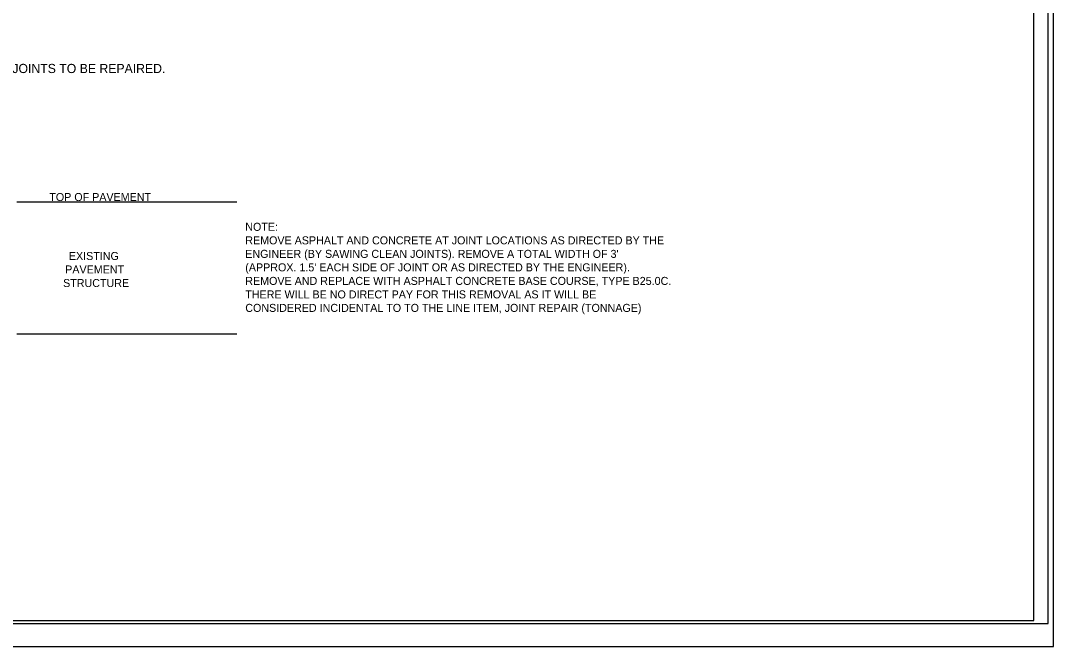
# Model space of a CAD drawing. Extents: x 2455709 to 2456046, y 594728 to 594947.
# Drawn here: x 2455864.9 to 2456045.5, y 594727.6 to 594837 of the extents above; entities that cross this region are included whole.
import ezdxf

# ---------------------------------------------------------------- set-up
doc = ezdxf.new("R2010")
doc.units = 0
for name, color, linetype in [('Default', 7, 'Continuous'), ('Old_Level_3', 7, 'Continuous'), ('Prop Horizontal Alignment', 7, 'Continuous'), ('Prop Roadway Culvert', 7, 'Continuous'), ('Prop Vertical Profile Grade', 7, 'Continuous')]:
    doc.layers.add(name, color=color, linetype=linetype)

msp = doc.modelspace()

# ---------------------------------------------------------------- linework, layer by layer
at = {"layer": 'Default'}
for p, q in [((2455864.2, 594805.32), (2455902.69, 594805.32)), ((2455864.2, 594805.32), (2455902.69, 594805.32)), ((2455864.2, 594782.22), (2455902.69, 594782.22)), ((2455864.2, 594782.22), (2455902.69, 594782.22))]:
    msp.add_line(p, q, dxfattribs=at)
at = {"layer": 'Prop Horizontal Alignment'}
msp.add_lwpolyline([(2456042.11, 594942.08), (2455742.1, 594942.08), (2455742.1, 594732.08), (2456042.11, 594732.08)], close=True, dxfattribs=at)
at = {"layer": 'Prop Roadway Culvert'}
msp.add_lwpolyline([(2455708.81, 594727.57), (2456045.51, 594727.57), (2456045.51, 594946.57), (2455708.81, 594946.57)], close=True, dxfattribs=at)
at = {"layer": 'Prop Vertical Profile Grade'}
msp.add_lwpolyline([(2455711.41, 594731.57), (2456044.6, 594731.58), (2456044.61, 594942.57), (2455711.41, 594942.57)], close=True, dxfattribs=at)

# ---------------------------------------------------------------- texts
at = {"layer": 'Default'}
for s, height, p in [("CONTRACTOR SHALL COORDINATE WITH RESIDENT ENGINEER'S OFFICE FOR LOCATION OF JOINTS TO BE REPAIRED.", 1.601, (2455765.7, 594827.83)), ("CONTRACTOR SHALL COORDINATE WITH RESIDENT ENGINEER'S OFFICE FOR LOCATION OF JOINTS TO BE REPAIRED.", 1.601, (2455765.7, 594827.83)), ('TOP OF PAVEMENT', 1.4007, (2455869.87, 594805.45)), ('TOP OF PAVEMENT', 1.4007, (2455869.87, 594805.45)), ('EXISTING', 1.401, (2455873.29, 594795.14)), ('EXISTING', 1.401, (2455873.29, 594795.14)), ('PAVEMENT', 1.401, (2455872.65, 594792.78)), ('PAVEMENT', 1.401, (2455872.65, 594792.78)), ('STRUCTURE', 1.401, (2455872.28, 594790.41)), ('STRUCTURE', 1.401, (2455872.28, 594790.41))]:
    msp.add_text(s, height=height, rotation=360, dxfattribs=at).set_placement(p)
at = {"layer": 'Old_Level_3'}
for s, height, p in [('NOTE:', 1.401, (2455904.15, 594800.24)), ('REMOVE ASPHALT AND CONCRETE AT JOINT LOCATIONS AS DIRECTED BY THE ', 1.4007, (2455904.15, 594797.87)), ("ENGINEER (BY SAWING CLEAN JOINTS). REMOVE A TOTAL WIDTH OF 3' ", 1.4007, (2455904.15, 594795.51)), ("(APPROX. 1.5' EACH SIDE OF JOINT OR AS DIRECTED BY THE ENGINEER). ", 1.4007, (2455904.15, 594793.15)), ('REMOVE AND REPLACE WITH ASPHALT CONCRETE BASE COURSE, TYPE B25.0C. ', 1.4007, (2455904.15, 594790.78)), ('THERE WILL BE NO DIRECT PAY FOR THIS REMOVAL AS IT WILL BE ', 1.4007, (2455904.15, 594788.42)), ('CONSIDERED INCIDENTAL TO TO THE LINE ITEM, JOINT REPAIR (TONNAGE)', 1.4007, (2455904.15, 594786.06))]:
    msp.add_text(s, height=height, rotation=360, dxfattribs=at).set_placement(p)

doc.saveas('drawing.dxf')
